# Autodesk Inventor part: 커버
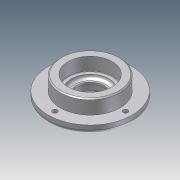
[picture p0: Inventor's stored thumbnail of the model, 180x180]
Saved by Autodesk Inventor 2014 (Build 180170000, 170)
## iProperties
Company: 한국ATC센터
Created: 2014-10
Part Number: 커버
Document SubType Name: Modeling
Designer: KYOUNG IL JANG
Density: 1 g/cm^3
Mass: 44.7286 g
Surface Area: 161.165 cm^2
Volume: 44.7286 cm^3
Material: 일반
Appearance: 기본값
Author: KYOUNG IL JANG
Revision Number: 1
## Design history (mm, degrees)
sketch "스케치1"
  geometry: C1 r 38 at (0, 0); 1 further point
  constraints: 1 centre point, 1 coincident
  dimensions: "d0" = 76 diameter of C1
extrude "돌출1" new body sketch "스케치1" distance "d1" = 7; taper "d2" = 0 deg
sketch "스케치2"
  geometry: C1 r 27 at (0, 0); 1 further point
  constraints: 1 centre point, 1 coincident
  dimensions: "d3" = 54 diameter of C1
extrude "돌출2" join sketch "스케치2" distance "d4" = 13; taper "d5" = 0 deg
sketch "스케치3"
  geometry: C1 r 20 at (0, 0); 1 further point
  constraints: 1 centre point, 1 coincident
  dimensions: "d6" = 40 diameter of C1
extrude "돌출3" join sketch "스케치3" distance "d7" = 5; taper "d8" = 0 deg
hole "구멍1" diameter "d11" = 25; stored, may be unused: countersink angle "d15" = 90 deg, drill point angle "d17" = 118 deg; dims "d9" = 10, "d10" = 10, "d12" = 6, "d13" = 32, "d14" = 8.3, "d16" = 8
hole "구멍2" diameter "d20" = 34; stored, may be unused: countersink angle "d24" = 90 deg, drill point angle "d26" = 0 deg; dims "d18" = 10, "d19" = 10, "d21" = 6, "d22" = 40, "d23" = 12, "d25" = 3
fillet "모깎기2" dims "d34" = 3
fillet "모깎기1" dims "d27" = 0.3
chamfer "모따기1" distance "d28" = 1; stored, may be unused: second distance "d29" = 2, angle "d30" = 45 deg
chamfer "모따기2" distance "d31" = 1.2; stored, may be unused: second distance "d32" = 2, angle "d33" = 30 deg
sketch "스케치4" dims "d35" = 64
  geometry: 3 further points
  constraints: 2 horizontal alignment, 1 coincident, 2 other
hole "구멍3" sketch "스케치4" at (32, 0) diameter "d36" = 4.5; stored, may be unused: countersink angle "d40" = 90 deg, drill point angle "d42" = 118 deg; dims "d37" = 6, "d38" = 8, "d39" = 4.4, "d41" = 13
node "솔리드1"
pattern_circular "원형 패턴1" dims angle "d44" = 360 deg
